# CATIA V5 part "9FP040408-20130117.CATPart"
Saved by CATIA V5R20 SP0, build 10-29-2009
Part number: 9FP040408-20130117
Revision: ANY
Definition: UNKNOWN
Nomenclature: 9FP040408-20130117
Source: Unknown
Bounding box of the stored display mesh (mm): x -4 to 4, y -4 to 4, z 0 to 6
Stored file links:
  C:\Users\Utente\Desktop\IO LAVORO\3D X SITO CF\CUMSA\3D files PF\PF 044150\9FP040408-20130117.CATPart
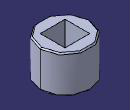
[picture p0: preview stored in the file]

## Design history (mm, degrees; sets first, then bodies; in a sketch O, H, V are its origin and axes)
Body1 "Chaflán1" (main body)
  Solid1: solid without history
